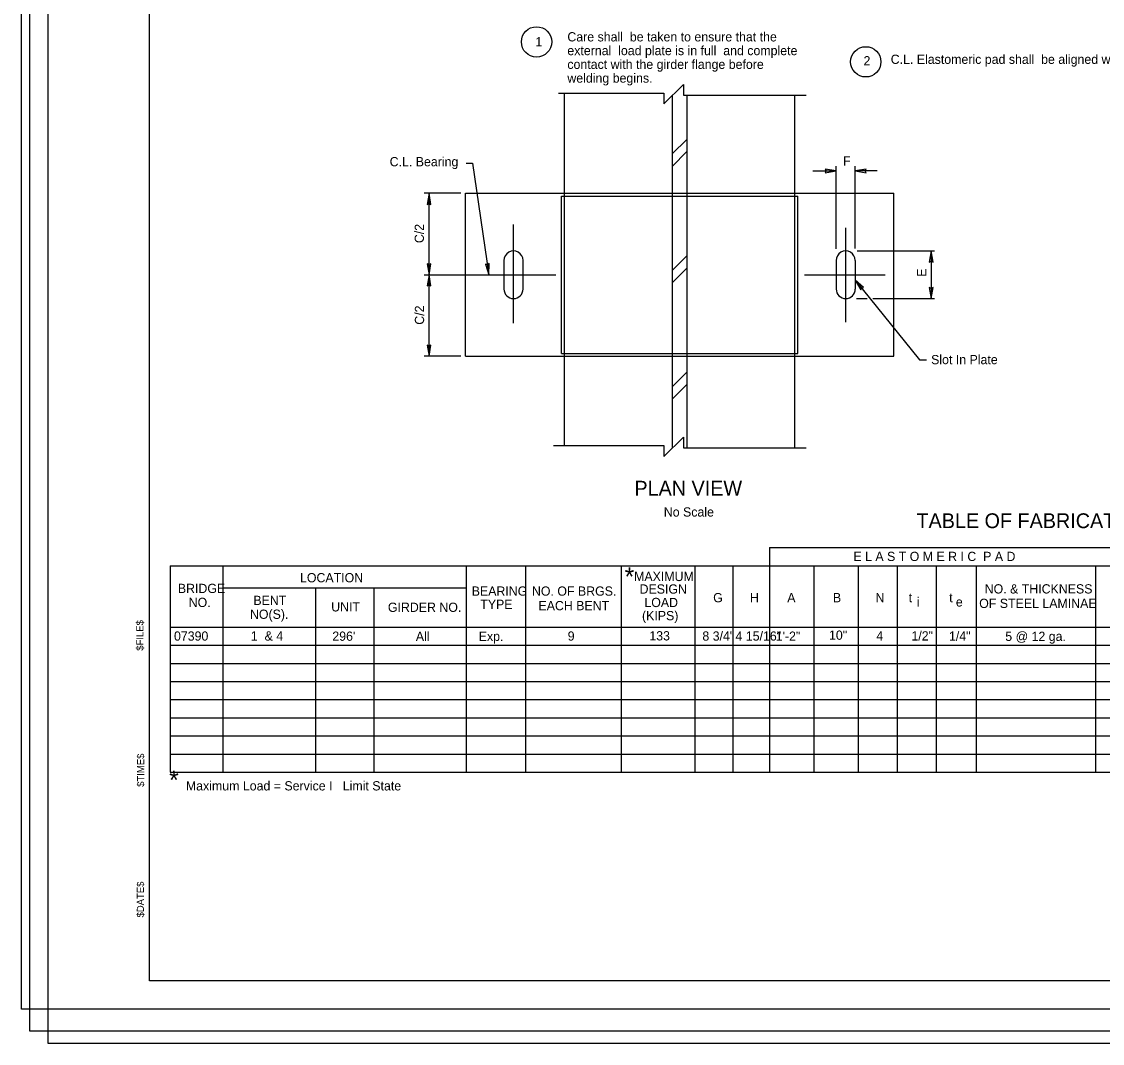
# Model space of a CAD drawing. Extents: x -194 to 226, y 505 to 725.
# Drawn here: x -193.6 to -47.4, y 505.4 to 643.6 of the extents above; entities that cross this region are included whole.
import ezdxf

# ---------------------------------------------------------------- set-up
doc = ezdxf.new("R2010")
doc.units = 0
for name, color, linetype in [('border', 7, 'Continuous'), ('Border 2660-Hwy18 - Level 62', 7, 'Continuous'), ('Border 2660-Hwy18 - Level 63', 7, 'Continuous'), ('Level 20', 7, 'Continuous'), ('Level 31', 7, 'Continuous'), ('Level 40', 7, 'Continuous'), ('Level 41', 7, 'Continuous'), ('Level 42', 7, 'Continuous'), ('Level 43', 7, 'Continuous'), ('Level 62 PDF', 7, 'Continuous')]:
    doc.layers.add(name, color=color, linetype=linetype)

msp = doc.modelspace()

# ---------------------------------------------------------------- linework, layer by layer
at = {"layer": 'border'}
for p, q in [((-176.33, 513.86), (-176.33, 719.31)), ((143.78, 513.86), (-176.33, 513.86))]:
    msp.add_line(p, q, dxfattribs=at)
at = {"layer": 'Border 2660-Hwy18 - Level 62'}
msp.add_lwpolyline([(-192.53, 725.17), (148.65, 725.17), (148.65, 507.07), (-192.53, 507.07)], close=True, dxfattribs=at)
at = {"layer": 'Border 2660-Hwy18 - Level 63'}
msp.add_lwpolyline([(-193.64, 723.74), (146.35, 723.74), (146.35, 510.04), (-193.64, 510.04)], close=True, dxfattribs=at)
at = {"layer": 'Level 20'}
for p, q in [((-127.1, 602.8), (-127.1, 616.17)), ((-82.15, 602.94), (-82.15, 615.72)), ((-139.16, 609.37), (-121.39, 609.37)), ((-87.71, 609.37), (-76.8, 609.37))]:
    msp.add_line(p, q, dxfattribs=at)
at = {"layer": 'Level 31'}
for p, q in [((-120.21, 586.27), (-120.21, 633.94)), ((-105.61, 633.62), (-105.61, 585.93)), ((-103.64, 633.66), (-103.64, 585.98)), ((-89.04, 585.98), (-89.04, 633.66)), ((-133.6, 598.35), (-133.6, 620.39)), ((-133.6, 620.39), (-120.21, 620.39)), ((-120.61, 598.74), (-120.61, 620)), ((-120.61, 620), (-88.65, 620)), ((-120.21, 620.39), (-89.04, 620.39)), ((-89.04, 620.39), (-75.66, 620.39)), ((-88.65, 598.74), (-88.65, 620)), ((-75.66, 598.35), (-75.66, 620.39)), ((-128.39, 611.3), (-128.39, 607.44)), ((-125.82, 611.3), (-125.82, 607.44)), ((-83.44, 611.3), (-83.44, 607.44)), ((-80.87, 611.3), (-80.87, 607.44)), ((-133.6, 598.35), (-120.21, 598.35)), ((-120.61, 598.74), (-88.65, 598.74)), ((-120.21, 598.35), (-89.04, 598.35)), ((-89.04, 598.35), (-75.66, 598.35))]:
    msp.add_line(p, q, dxfattribs=at)
for centre, start, end in [((-127.1, 611.3), 0, 180.0422), ((-82.15, 611.3), 0, 180.0422), ((-127.1, 607.44), 180.0422, 0), ((-82.15, 607.44), 180.0422, 0)]:
    msp.add_arc(centre, 1.29, start, end, dxfattribs=at)
at = {"layer": 'Level 40'}
for p, q in [((-166.4, 570.01), (-166.4, 542.09)), ((-133.5, 570.01), (-133.5, 542.09)), ((-125.49, 570.01), (-125.49, 542.09)), ((-112.53, 570.01), (-112.53, 542.09)), ((-102.55, 570.01), (-102.55, 542.09)), ((-97.43, 570.01), (-97.43, 542.09)), ((-86.47, 570.01), (-86.47, 542.09)), ((-80.45, 570.01), (-80.45, 542.09)), ((-75.17, 570.01), (-75.17, 542.09)), ((-69.89, 570.01), (-69.89, 542.09)), ((-64.51, 570.01), (-64.51, 542.09)), ((-48.37, 570.01), (-48.37, 542.09)), ((-102.55, 567.56), (-102.55, 547)), ((-166.4, 567.03), (-133.5, 567.03)), ((-153.9, 567.03), (-153.9, 542.09)), ((-146, 567.03), (-146, 542.09)), ((-173.56, 561.72), (58.08, 561.72)), ((-173.56, 559.27), (58.08, 559.27)), ((-173.56, 556.81), (58.08, 556.81)), ((-173.56, 556.81), (58.08, 556.81)), ((-173.56, 554.36), (58.08, 554.36)), ((-173.56, 554.36), (58.08, 554.36)), ((-173.56, 551.91), (58.08, 551.91)), ((-173.56, 551.91), (58.08, 551.91)), ((-173.56, 549.45), (58.08, 549.45)), ((-173.56, 547), (58.08, 547)), ((-173.56, 544.54), (58.08, 544.54))]:
    msp.add_line(p, q, dxfattribs=at)
for centre in [(-123.98, 640.87), (-79.43, 638.17)]:
    msp.add_circle(centre, 2.05, dxfattribs=at)
at = {"layer": 'Level 41'}
for p, q in [((-92.48, 572.46), (-92.48, 542.09)), ((-92.48, 572.46), (58.08, 572.46)), ((-173.56, 570.01), (58.08, 570.01)), ((-173.56, 570.01), (-173.56, 542.09)), ((-173.56, 542.09), (58.08, 542.09))]:
    msp.add_line(p, q, dxfattribs=at)
at = {"layer": 'Level 42'}
for p, q in [((-105.61, 625.71), (-103.64, 627.67)), ((-105.61, 624.03), (-103.64, 626.02)), ((-105.61, 609.96), (-103.64, 611.93)), ((-105.61, 608.28), (-103.64, 610.28)), ((-105.61, 594.22), (-103.64, 596.19)), ((-105.61, 592.54), (-103.64, 594.53))]:
    msp.add_line(p, q, dxfattribs=at)
at = {"layer": 'Level 43'}
for p, q in [((-86.59, 623.42), (-83.44, 623.42)), ((-83.44, 612.86), (-83.44, 624.07)), ((-80.87, 612.91), (-80.87, 624.07)), ((-77.9, 623.42), (-80.87, 623.42)), ((-134.24, 620.39), (-139.16, 620.39)), ((-138.52, 609.37), (-138.52, 620.39)), ((-80.62, 612.59), (-70.14, 612.59)), ((-70.59, 612.59), (-70.59, 606.16)), ((-138.52, 598.35), (-138.52, 609.37)), ((-80.71, 606.16), (-79.23, 606.16)), ((-78.47, 606.16), (-70.14, 606.16)), ((-134.24, 598.35), (-139.16, 598.35))]:
    msp.add_line(p, q, dxfattribs=at)
for points in [[(-121, 633.94), (-106.74, 633.94), (-106.74, 632.5), (-104.11, 635.11), (-104.11, 633.66), (-87.51, 633.66)], [(-133.48, 624.45), (-132.64, 624.45), (-130.42, 609.37)], [(-80.87, 608.64), (-72.15, 597.88), (-71.24, 597.88)], [(-121.67, 586.27), (-106.74, 586.27), (-106.74, 584.81), (-104.11, 587.42), (-104.11, 585.98), (-87.51, 585.98)]]:
    msp.add_lwpolyline(points, dxfattribs=at)
for points in [[(-83.44, 623.42), (-84.94, 623.67), (-84.81, 623.42), (-84.94, 623.17)], [(-80.87, 623.42), (-79.37, 623.17), (-79.5, 623.42), (-79.37, 623.67)], [(-138.52, 620.39), (-138.77, 618.89), (-138.52, 619.02), (-138.27, 618.89)], [(-70.59, 612.59), (-70.84, 611.09), (-70.59, 611.22), (-70.34, 611.09)], [(-138.52, 609.37), (-138.27, 610.87), (-138.52, 610.74), (-138.77, 610.87)], [(-130.42, 609.37), (-130.39, 610.89), (-130.62, 610.73), (-130.89, 610.82)], [(-138.52, 609.37), (-138.77, 607.87), (-138.52, 608), (-138.27, 607.87)], [(-80.87, 608.64), (-80.12, 607.31), (-80, 607.57), (-79.73, 607.63)], [(-70.59, 606.16), (-70.34, 607.66), (-70.59, 607.53), (-70.84, 607.66)], [(-138.52, 598.35), (-138.27, 599.85), (-138.52, 599.72), (-138.77, 599.85)]]:
    msp.add_lwpolyline(points, close=True, dxfattribs=at)
at = {"layer": 'Level 62 PDF'}
msp.add_lwpolyline([(-190.03, 723.5), (151.15, 723.5), (151.15, 505.41), (-190.03, 505.41)], close=True, dxfattribs=at)

# ---------------------------------------------------------------- texts
at = {"layer": 'border'}
for s, p in [('$FILE$', (-177.16, 558.52)), ('$TIME$', (-177.06, 540.11)), ('$DATE$', (-177.1, 522.44))]:
    msp.add_text(s, height=0.96, rotation=89.9999, dxfattribs=at).set_placement(p)
at = {"layer": 'Level 40'}
for s, height, p in [('Care shall  be taken to ensure that the', 1.25, (-119.81, 640.93)), ('1', 1.25, (-124.14, 640.26)), ('external  load plate is in full  and complete', 1.25, (-119.81, 639.07)), ('C.L. Elastomeric pad shall  be aligned with C.L. Girder.', 1.25, (-76.06, 637.89)), ('contact with the girder flange before', 1.25, (-119.81, 637.21)), ('2', 1.25, (-79.74, 637.69)), ('welding begins.', 1.25, (-119.81, 635.35)), ('C.L. Bearing', 1.25, (-143.85, 624.04)), ('F', 1.25, (-82.51, 624.14)), ('Slot In Plate', 1.25, (-70.6, 597.27)), ('No Scale', 1.25, (-106.76, 576.66)), ('E L A S T O M E R I C  P A D', 1.25, (-81.11, 570.65)), ('LOCATION', 1.25, (-155.98, 567.77)), ('*', 2.5, (-112.06, 567.3)), ('MAXIMUM', 1.25, (-110.78, 567.94)), ('BRIDGE', 1.25, (-172.51, 566.32)), ('DESIGN', 1.25, (-110.04, 566.24)), ('NO. & THICKNESS', 1.25, (-63.35, 566.26)), ('BENT', 1.25, (-162.29, 564.7)), ('BEARING', 1.25, (-132.75, 565.96)), ('NO. OF BRGS.', 1.25, (-124.6, 565.96)), ('G', 1.25, (-100.08, 565.07)), ('H', 1.25, (-95.11, 565.07)), ('A', 1.25, (-90.06, 565.07)), ('B', 1.25, (-83.88, 565.07)), ('N', 1.25, (-78.12, 565.07)), ('t ', 1.25, (-73.63, 565.07)), ('t ', 1.25, (-68.15, 565.07)), ('NO.', 1.25, (-171.04, 564.43)), ('UNIT', 1.25, (-151.76, 563.83)), ('GIRDER NO.', 1.25, (-144.09, 563.77)), ('TYPE', 1.25, (-131.59, 564.17)), ('EACH BENT', 1.25, (-123.72, 563.99)), ('LOAD', 1.25, (-109.39, 564.42)), ('i', 1.25, (-72.52, 564.49)), ('e', 1.25, (-67.25, 564.49)), ('OF STEEL LAMINAE', 1.25, (-64.09, 564.3)), ('NO(S).', 1.25, (-162.75, 562.83)), ('(KIPS)', 1.25, (-109.71, 562.64)), ('07390', 1.25, (-173.03, 559.88)), ('1  & 4', 1.25, (-162.63, 559.89)), ("296'", 1.25, (-151.61, 559.86)), ('All', 1.25, (-140.31, 559.84)), ('Exp.', 1.25, (-131.8, 559.84)), ('9', 1.25, (-119.76, 559.88)), ('133', 1.25, (-108.72, 559.91)), ('8 3/4"', 1.25, (-101.54, 559.88)), ('4 15/16"', 1.25, (-97.06, 559.88)), ('1\'-2"', 1.25, (-91.62, 559.86)), ('10"', 1.25, (-84.41, 560)), ('4', 1.25, (-78.01, 559.9)), ('1/2"', 1.25, (-73.26, 559.9)), ('1/4"', 1.25, (-68.18, 559.87)), ('5 @ 12 ga.', 1.25, (-60.56, 559.84)), ('*', 2.5, (-173.69, 539.79)), ('Maximum Load = Service I   Limit State', 1.25, (-171.42, 539.62))]:
    msp.add_text(s, height=height, dxfattribs=at).set_placement(p)
for s, p in [('C/2', (-139.22, 613.65)), ('E', (-71.24, 609.09)), ('C/2', (-139.19, 602.61))]:
    msp.add_text(s, height=1.25, rotation=90, dxfattribs=at).set_placement(p)
at = {"layer": 'Level 41'}
for s, p in [(' PLAN VIEW ', (-111.48, 579.5)), (' TABLE OF FABRICATOR VARIABLES ', (-73.32, 575.1))]:
    msp.add_text(s, height=2, dxfattribs=at).set_placement(p)

doc.saveas('drawing.dxf')
